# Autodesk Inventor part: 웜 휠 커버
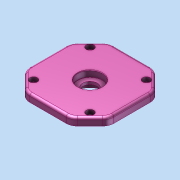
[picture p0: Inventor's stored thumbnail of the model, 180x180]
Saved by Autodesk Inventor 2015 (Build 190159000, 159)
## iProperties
Created: 2026-02
Part Number: 웜 휠 커버
Material: 일반
Document SubType Name: Modeling
Designer: Administrator
Density: 1 g/cm^3
Appearance: 기본값
Author: Administrator
Author: jhkim
Creation Date: 2026-01-30
Sending System: Autodesk Inventor 2026
Preprocessor: ST-DEVELOPER v20.1
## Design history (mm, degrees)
node "웜 휠 커버1"
node "솔리드1"
node "기준1"
